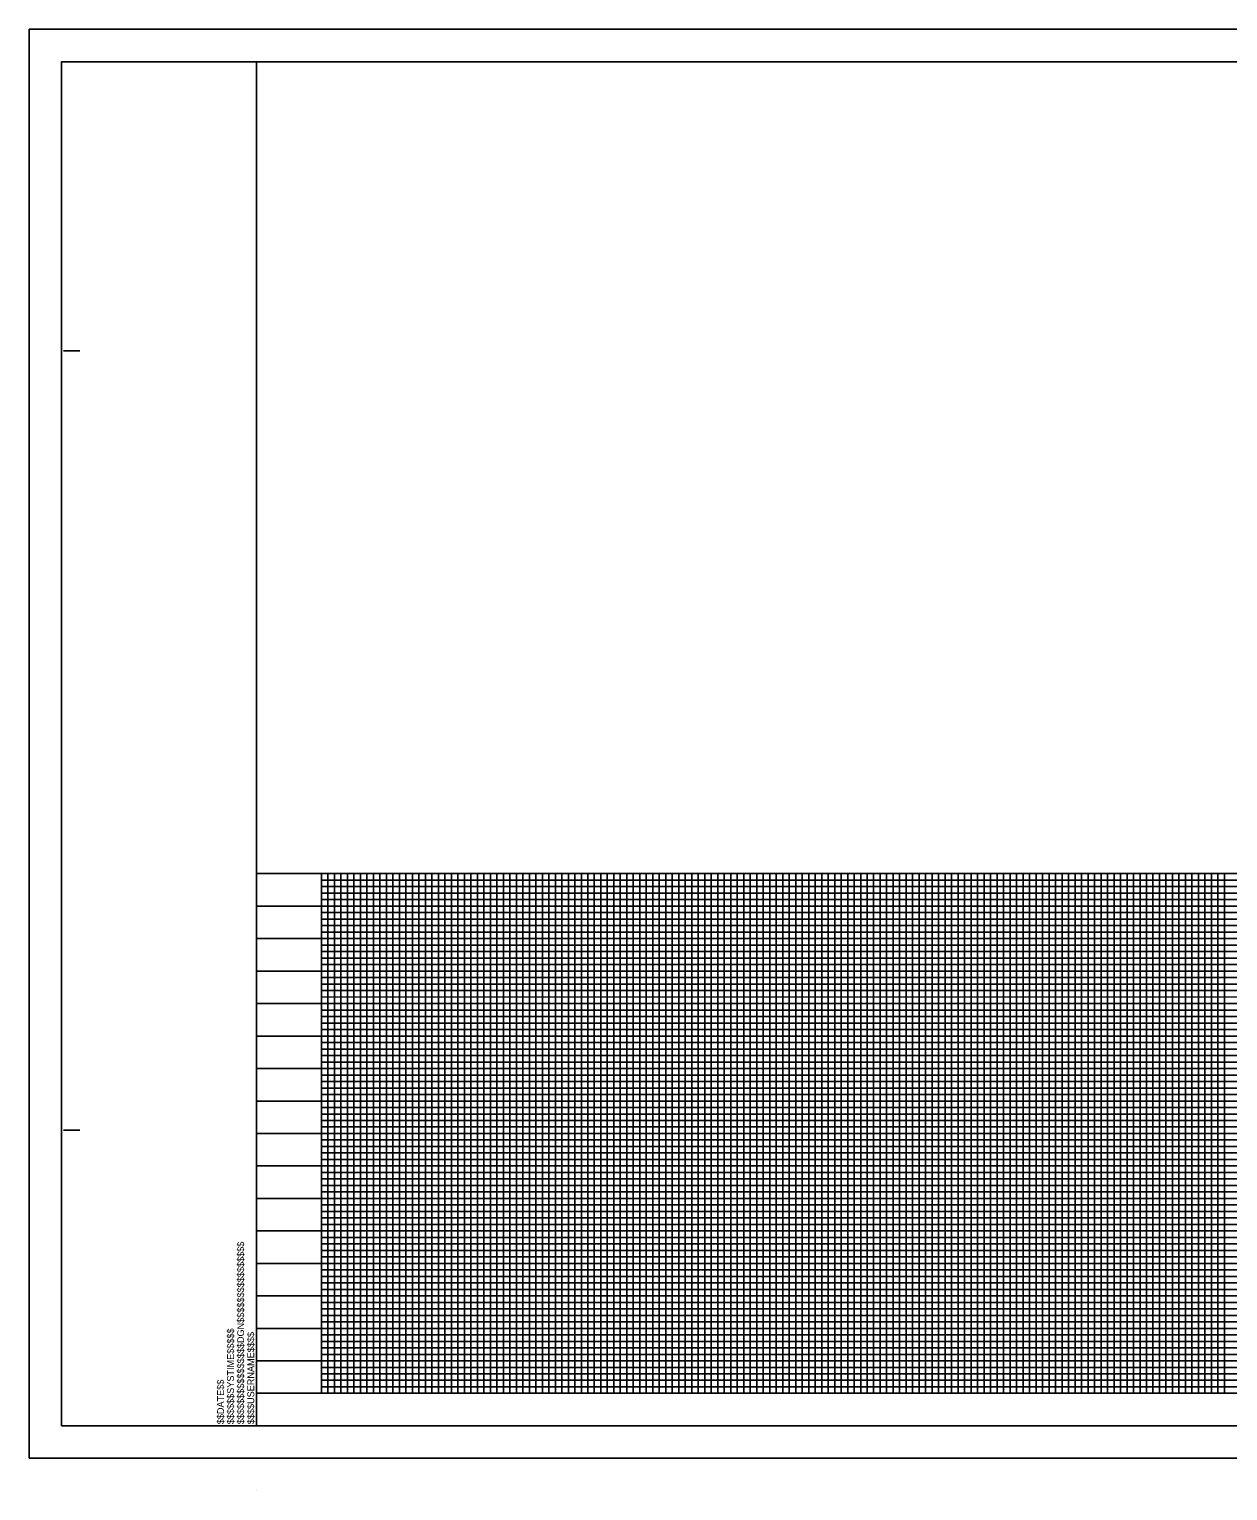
# Model space of a CAD drawing. Extents: x 2467493 to 2469405, y 649467 to 650592.
# Drawn here: x 2467493 to 2468415, y 649467 to 650592 of the extents above; entities that cross this region are included whole.
import ezdxf

# ---------------------------------------------------------------- set-up
doc = ezdxf.new("R2010")
doc.units = 0
for name, color, linetype in [('Old_Level_18', 7, 'Continuous'), ('Old_Level_40', 7, 'Continuous'), ('Old_Level_41', 7, 'Continuous'), ('Old_Level_42', 7, 'Continuous'), ('Old_Level_43', 7, 'Continuous'), ('Old_Level_46', 7, 'Continuous'), ('Old_Level_62', 7, 'Continuous'), ('Old_Level_63', 7, 'Continuous'), ('Sheet Clip Boundary CELL', 7, 'Continuous')]:
    doc.layers.add(name, color=color, linetype=linetype)

msp = doc.modelspace()

# ---------------------------------------------------------------- linework, layer by layer
at = {"layer": 'Old_Level_18'}
msp.add_line((2467667.5, 649517.5), (2467667.5, 649517.5), dxfattribs=at)
msp.add_line((2467667.5, 649517.5), (2467667.5, 649517.5), dxfattribs=at)
msp.add_line((2467667.5, 649517.5), (2467667.5, 649517.5), dxfattribs=at)
msp.add_lwpolyline([(2469167.5, 650567.5), (2467667.5, 650567.5), (2467667.5, 649517.5), (2469167.5, 649517.5)], close=True, dxfattribs=at)
at = {"layer": 'Old_Level_40'}
msp.add_line((2467667.5, 649517.5), (2467667.5, 649517.5), dxfattribs=at)
msp.add_line((2467667.5, 649517.5), (2467667.5, 649517.5), dxfattribs=at)
msp.add_line((2467667.5, 649517.5), (2467667.5, 649517.5), dxfattribs=at)
msp.add_line((2467667.5, 649517.5), (2467667.5, 649517.5), dxfattribs=at)
msp.add_line((2467667.5, 649517.5), (2467667.5, 649517.5), dxfattribs=at)
at = {"layer": 'Old_Level_41'}
for p, q in [((2467519, 650345), (2467531.5, 650345)), ((2467667.5, 649942.5), (2469167.5, 649942.5)), ((2467519, 649745), (2467531.5, 649745)), ((2469167.5, 649542.5), (2467667.5, 649542.5))]:
    msp.add_line(p, q, dxfattribs=at)
for points in [[(2469167.5, 649942.5), (2467667.5, 649942.5), (2467667.5, 649892.5), (2469167.5, 649892.5)], [(2467717.5, 649942.5), (2467717.5, 649542.5), (2467767.5, 649542.5), (2467767.5, 649942.5)], [(2467817.5, 649942.5), (2467817.5, 649542.5), (2467867.5, 649542.5), (2467867.5, 649942.5)], [(2467917.5, 649942.5), (2467917.5, 649542.5), (2467967.5, 649542.5), (2467967.5, 649942.5)], [(2468017.5, 649942.5), (2468017.5, 649542.5), (2468067.5, 649542.5), (2468067.5, 649942.5)], [(2468117.5, 649942.5), (2468117.5, 649542.5), (2468167.5, 649542.5), (2468167.5, 649942.5)], [(2468217.5, 649942.5), (2468217.5, 649542.5), (2468267.5, 649542.5), (2468267.5, 649942.5)], [(2468317.5, 649942.5), (2468317.5, 649542.5), (2468367.5, 649542.5), (2468367.5, 649942.5)], [(2469167.5, 649842.5), (2467667.5, 649842.5), (2467667.5, 649792.5), (2469167.5, 649792.5)], [(2469167.5, 649742.5), (2467667.5, 649742.5), (2467667.5, 649692.5), (2469167.5, 649692.5)], [(2469167.5, 649642.5), (2467667.5, 649642.5), (2467667.5, 649642.5), (2467667.5, 649592.5), (2469167.5, 649592.5)], [(2467705, 649517.5), (2467705, 649517.5)]]:
    msp.add_lwpolyline(points, dxfattribs=at)
at = {"layer": 'Old_Level_42'}
msp.add_line((2467667.5, 649542.5), (2467667.5, 649542.5), dxfattribs=at)
for points in [[(2467667.5, 649942.5), (2467667.5, 649917.5), (2469167.5, 649917.5)], [(2467742.5, 649942.5), (2467742.5, 649542.5), (2467792.5, 649542.5), (2467792.5, 649942.5)], [(2467842.5, 649942.5), (2467842.5, 649542.5), (2467892.5, 649542.5), (2467892.5, 649942.5)], [(2467942.5, 649942.5), (2467942.5, 649542.5), (2467992.5, 649542.5), (2467992.5, 649942.5)], [(2468042.5, 649942.5), (2468042.5, 649542.5), (2468092.5, 649542.5), (2468092.5, 649942.5)], [(2468142.5, 649942.5), (2468142.5, 649542.5), (2468192.5, 649542.5), (2468192.5, 649942.5)], [(2468242.5, 649942.5), (2468242.5, 649542.5), (2468292.5, 649542.5), (2468292.5, 649542.5), (2468292.5, 649942.5)], [(2468342.5, 649942.5), (2468342.5, 649542.5), (2468392.5, 649542.5), (2468392.5, 649942.5)], [(2469167.5, 649867.5), (2467667.5, 649867.5), (2467667.5, 649817.5), (2469167.5, 649817.5)], [(2469167.5, 649767.5), (2467667.5, 649767.5), (2467667.5, 649717.5), (2469167.5, 649717.5)], [(2469167.5, 649667.5), (2467667.5, 649667.5), (2467667.5, 649617.5), (2469167.5, 649617.5)], [(2469167.5, 649567.5), (2467667.5, 649567.5)], [(2469167.5, 649542.5), (2467667.5, 649542.5)]]:
    msp.add_lwpolyline(points, dxfattribs=at)
at = {"layer": 'Old_Level_43'}
for p, q in [((2467717.5, 649937.5), (2469117.5, 649937.5)), ((2469117.5, 649932.5), (2467717.5, 649932.5)), ((2467717.5, 649927.5), (2469117.5, 649927.5)), ((2469117.5, 649922.5), (2467717.5, 649922.5)), ((2467717.5, 649912.5), (2469117.5, 649912.5)), ((2469117.5, 649907.5), (2467717.5, 649907.5)), ((2467717.5, 649902.5), (2469117.5, 649902.5)), ((2469117.5, 649897.5), (2467717.5, 649897.5)), ((2467717.5, 649887.5), (2469117.5, 649887.5)), ((2469117.5, 649882.5), (2467717.5, 649882.5)), ((2467717.5, 649877.5), (2469117.5, 649877.5)), ((2469117.5, 649872.5), (2467717.5, 649872.5)), ((2467717.5, 649862.5), (2469117.5, 649862.5)), ((2469117.5, 649857.5), (2467717.5, 649857.5)), ((2467717.5, 649852.5), (2469117.5, 649852.5)), ((2469117.5, 649847.5), (2467717.5, 649847.6)), ((2467717.5, 649837.5), (2469117.5, 649837.5)), ((2469117.5, 649832.5), (2467717.5, 649832.5)), ((2467717.5, 649827.5), (2469117.5, 649827.5)), ((2469117.5, 649822.5), (2467717.5, 649822.5)), ((2467717.5, 649812.5), (2469117.5, 649812.5)), ((2469117.5, 649807.5), (2467717.5, 649807.5)), ((2467717.5, 649802.5), (2469117.5, 649802.5)), ((2469117.5, 649797.5), (2467717.5, 649797.5)), ((2467717.5, 649787.5), (2469117.5, 649787.5)), ((2469117.5, 649782.5), (2467717.5, 649782.5)), ((2467717.5, 649777.5), (2469117.5, 649777.5)), ((2469117.5, 649772.5), (2467717.5, 649772.5)), ((2467717.5, 649762.5), (2469117.5, 649762.5)), ((2469117.5, 649757.5), (2467717.5, 649757.5)), ((2467717.5, 649752.5), (2469117.5, 649752.5)), ((2469117.5, 649747.5), (2467717.5, 649747.5)), ((2467717.5, 649737.5), (2469117.5, 649737.5)), ((2469117.5, 649732.5), (2467717.5, 649732.5)), ((2467717.5, 649727.5), (2469117.5, 649727.5)), ((2469117.5, 649722.5), (2467717.5, 649722.5)), ((2467717.5, 649712.5), (2469117.5, 649712.5)), ((2469117.5, 649707.5), (2467717.5, 649707.5)), ((2467717.5, 649702.5), (2469117.5, 649702.5)), ((2469117.5, 649697.5), (2467717.5, 649697.5)), ((2467717.5, 649687.5), (2469117.5, 649687.5)), ((2469117.5, 649682.5), (2467717.5, 649682.5)), ((2467717.5, 649677.5), (2469117.5, 649677.5)), ((2469117.5, 649672.5), (2467717.5, 649672.5)), ((2467717.5, 649662.5), (2469117.5, 649662.5)), ((2469117.5, 649657.5), (2467717.5, 649657.5)), ((2467717.5, 649652.5), (2469117.5, 649652.5)), ((2469117.5, 649647.5), (2467717.5, 649647.5)), ((2467717.5, 649637.5), (2469117.5, 649637.5)), ((2469117.5, 649632.5), (2467717.5, 649632.5)), ((2467717.5, 649627.5), (2469117.5, 649627.5)), ((2469117.5, 649622.5), (2467717.5, 649622.5)), ((2467717.5, 649612.5), (2469117.5, 649612.5)), ((2469117.5, 649607.5), (2467717.5, 649607.5)), ((2467717.5, 649602.5), (2469117.5, 649602.5)), ((2469117.5, 649597.5), (2467717.5, 649597.5)), ((2467717.5, 649587.5), (2469117.5, 649587.5)), ((2469117.5, 649582.5), (2467717.5, 649582.5)), ((2467717.5, 649577.5), (2469117.5, 649577.5)), ((2469117.5, 649572.5), (2467717.5, 649572.5)), ((2467717.5, 649562.5), (2469117.5, 649562.5)), ((2469117.5, 649557.5), (2467717.5, 649557.5)), ((2467717.5, 649552.5), (2469117.5, 649552.5)), ((2467717.5, 649547.5), (2469117.5, 649547.5))]:
    msp.add_line(p, q, dxfattribs=at)
for points in [[(2467722.5, 649942.5), (2467722.5, 649542.5), (2467727.5, 649542.5), (2467727.5, 649942.5)], [(2467732.5, 649942.5), (2467732.5, 649542.5), (2467737.5, 649542.5), (2467737.5, 649942.5)], [(2467747.5, 649942.5), (2467747.5, 649542.5), (2467752.5, 649542.5), (2467752.5, 649942.5)], [(2467757.5, 649942.5), (2467757.5, 649542.5), (2467762.5, 649542.5), (2467772.5, 649542.5), (2467777.5, 649542.5), (2467777.5, 649942.5)], [(2467762.5, 649542.5), (2467762.5, 649942.5)], [(2467772.5, 649942.5), (2467772.5, 649542.5)], [(2467782.5, 649942.5), (2467782.5, 649542.5), (2467787.5, 649542.5), (2467787.5, 649942.5)], [(2467797.5, 649942.5), (2467797.5, 649542.5), (2467802.5, 649542.5), (2467802.5, 649942.5)], [(2467807.5, 649942.5), (2467807.5, 649542.5), (2467812.5, 649542.5), (2467812.5, 649942.5)], [(2467822.5, 649942.5), (2467822.5, 649542.5), (2467827.5, 649542.5), (2467827.5, 649942.5)], [(2467832.5, 649942.5), (2467832.5, 649542.5), (2467837.5, 649542.5), (2467837.5, 649942.5)], [(2467847.5, 649942.5), (2467847.5, 649542.5), (2467852.5, 649542.5), (2467852.5, 649942.5)], [(2467857.5, 649942.5), (2467857.5, 649542.5), (2467862.5, 649542.5), (2467862.5, 649942.5)], [(2467872.5, 649942.5), (2467872.5, 649542.5), (2467877.5, 649542.5), (2467877.5, 649942.5)], [(2467882.5, 649942.5), (2467882.5, 649542.5), (2467887.5, 649542.5), (2467887.5, 649942.5)], [(2467897.5, 649942.5), (2467897.5, 649542.5), (2467902.5, 649542.5), (2467902.5, 649942.5)], [(2467907.5, 649942.5), (2467907.5, 649542.5), (2467912.5, 649542.5), (2467912.5, 649942.5)], [(2467922.5, 649942.5), (2467922.5, 649542.5), (2467927.5, 649542.5), (2467927.5, 649942.5)], [(2467932.5, 649542.5), (2467937.5, 649542.5), (2467937.5, 649942.5)], [(2467932.5, 649942.5), (2467932.5, 649542.5)], [(2467947.5, 649942.5), (2467947.5, 649542.5), (2467952.5, 649542.5), (2467952.5, 649942.5)], [(2467957.5, 649942.5), (2467957.5, 649542.5), (2467962.5, 649542.5), (2467962.5, 649942.5)], [(2467972.5, 649942.5), (2467972.5, 649542.5), (2467977.5, 649542.5), (2467977.5, 649942.5)], [(2467982.5, 649942.5), (2467982.5, 649542.5), (2467987.5, 649542.5), (2467987.5, 649942.5)], [(2467997.5, 649942.5), (2467997.5, 649542.5), (2468002.5, 649542.5), (2468002.5, 649942.5)], [(2468007.5, 649942.5), (2468007.5, 649542.5), (2468012.5, 649542.5), (2468012.5, 649942.5)], [(2468022.5, 649942.5), (2468022.5, 649542.5), (2468027.5, 649542.5), (2468027.5, 649942.5)], [(2468032.5, 649942.5), (2468032.5, 649542.5), (2468037.5, 649542.5), (2468037.5, 649942.5)], [(2468047.5, 649942.5), (2468047.5, 649542.5), (2468052.5, 649542.5), (2468052.5, 649942.5)], [(2468057.5, 649942.5), (2468057.5, 649542.5), (2468062.5, 649542.5), (2468062.5, 649942.5)], [(2468072.5, 649942.5), (2468072.5, 649542.5), (2468077.5, 649542.5), (2468077.5, 649942.5)], [(2468082.5, 649942.5), (2468082.5, 649542.5), (2468087.5, 649542.5), (2468087.5, 649942.5)], [(2468097.5, 649942.5), (2468097.5, 649542.5), (2468102.5, 649542.5), (2468102.5, 649942.5)], [(2468107.5, 649942.5), (2468107.5, 649542.5), (2468112.5, 649542.5), (2468112.5, 649942.5)], [(2468122.5, 649942.5), (2468122.5, 649542.5), (2468127.5, 649542.5), (2468127.5, 649942.5)], [(2468132.5, 649942.5), (2468132.5, 649542.5), (2468137.5, 649542.5), (2468137.5, 649942.5)], [(2468147.5, 649942.5), (2468147.5, 649542.5), (2468152.5, 649542.5), (2468152.5, 649942.5)], [(2468157.5, 649942.5), (2468157.5, 649542.5), (2468162.5, 649542.5), (2468162.5, 649942.5)], [(2468172.5, 649942.5), (2468172.5, 649542.5), (2468177.5, 649542.5), (2468177.5, 649942.5)], [(2468182.5, 649942.5), (2468182.5, 649542.5), (2468187.5, 649542.5), (2468187.5, 649942.5)], [(2468197.5, 649942.5), (2468197.5, 649542.5), (2468202.5, 649542.5), (2468202.5, 649942.5)], [(2468207.5, 649942.5), (2468207.5, 649542.5), (2468212.5, 649542.5), (2468212.5, 649942.5)], [(2468222.5, 649942.5), (2468222.5, 649542.5), (2468227.5, 649542.5), (2468227.5, 649942.5)], [(2468232.5, 649942.5), (2468232.5, 649542.5), (2468237.5, 649542.5), (2468237.5, 649942.5)], [(2468247.5, 649942.5), (2468247.5, 649542.5), (2468252.5, 649542.5), (2468252.5, 649942.5)], [(2468257.5, 649942.5), (2468257.5, 649542.5), (2468262.5, 649542.5), (2468262.5, 649942.5)], [(2468272.5, 649942.5), (2468272.5, 649542.5), (2468277.5, 649542.5), (2468277.5, 649942.5)], [(2468282.5, 649942.5), (2468282.5, 649542.5), (2468287.5, 649542.5), (2468287.5, 649942.5)], [(2468297.5, 649942.5), (2468297.5, 649542.5), (2468302.5, 649542.5), (2468302.5, 649942.5)], [(2468307.5, 649942.5), (2468307.5, 649542.5), (2468312.5, 649542.5), (2468312.5, 649942.5)], [(2468322.5, 649942.5), (2468322.5, 649542.5), (2468327.5, 649542.5), (2468327.5, 649942.5)], [(2468332.5, 649942.5), (2468332.5, 649542.5), (2468337.5, 649542.5), (2468337.5, 649942.5)], [(2468347.5, 649942.5), (2468347.5, 649542.5), (2468352.5, 649542.5), (2468352.5, 649942.5)], [(2468357.5, 649942.5), (2468357.5, 649542.5), (2468362.5, 649542.5), (2468362.5, 649942.5)], [(2468372.5, 649942.5), (2468372.5, 649542.5), (2468372.5, 649542.5), (2468377.5, 649542.5), (2468377.5, 649942.5)], [(2468382.5, 649942.5), (2468382.5, 649542.5), (2468387.5, 649542.5), (2468387.5, 649942.5)], [(2468397.5, 649942.5), (2468397.5, 649542.5), (2468402.5, 649542.5), (2468402.5, 649942.5)], [(2468407.5, 649942.5), (2468407.5, 649542.5), (2468412.5, 649542.5), (2468412.5, 649942.5)]]:
    msp.add_lwpolyline(points, dxfattribs=at)
at = {"layer": 'Old_Level_46'}
for p, q in [((2467667.5, 650567.5), (2467667.5, 650567.5)), ((2467667.5, 649467.5), (2467667.5, 649467.5))]:
    msp.add_line(p, q, dxfattribs=at)
at = {"layer": 'Old_Level_62'}
msp.add_line((2467517.5, 649517.5), (2467517.5, 649517.5), dxfattribs=at)
msp.add_lwpolyline([(2467517.5, 649517.5), (2469167.5, 649517.5), (2469167.5, 650567.5), (2467517.5, 650567.5)], close=True, dxfattribs=at)
at = {"layer": 'Old_Level_63'}
msp.add_line((2467492.5, 649492.5), (2467492.5, 649492.5), dxfattribs=at)
msp.add_lwpolyline([(2467492.5, 649492.5), (2469192.5, 649492.5), (2469192.5, 650592.5), (2467492.5, 650592.5)], close=True, dxfattribs=at)
at = {"layer": 'Sheet Clip Boundary CELL'}
msp.add_lwpolyline([(2467667.5, 650567.5), (2468967.5, 650567.5), (2468967.5, 650310.9), (2469167.5, 650310.9), (2469167.5, 649942.5), (2467667.5, 649942.5)], close=True, dxfattribs=at)

# ---------------------------------------------------------------- texts
at = {"layer": 'Old_Level_41'}
for s, p in [('$$$$$$$$$$$$$$$$DGN$$$$$$$$$$$$$$$$', (2467657.9, 649518.7)), ('$$$$$$SYSTIME$$$$$', (2467650.1, 649518.7)), ('$$$$USERNAME$$$$', (2467665.7, 649518.7)), ('$$DATE$$', (2467642.4, 649518.7))]:
    msp.add_text(s, height=5.25, rotation=90, dxfattribs=at).set_placement(p)

doc.saveas('drawing.dxf')
